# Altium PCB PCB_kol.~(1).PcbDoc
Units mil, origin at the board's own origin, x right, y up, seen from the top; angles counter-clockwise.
Board outline 2952.76 x 2952.76 mil, 4 copper layers (Top Layer, Mid 1 - POWER, Mid 2 - GND, Bottom Layer), stack 61.89 mil thick; 5 components, 17 nets, 134 pads, 1 vias.
Unrouted connection lines stored in the file: 3.
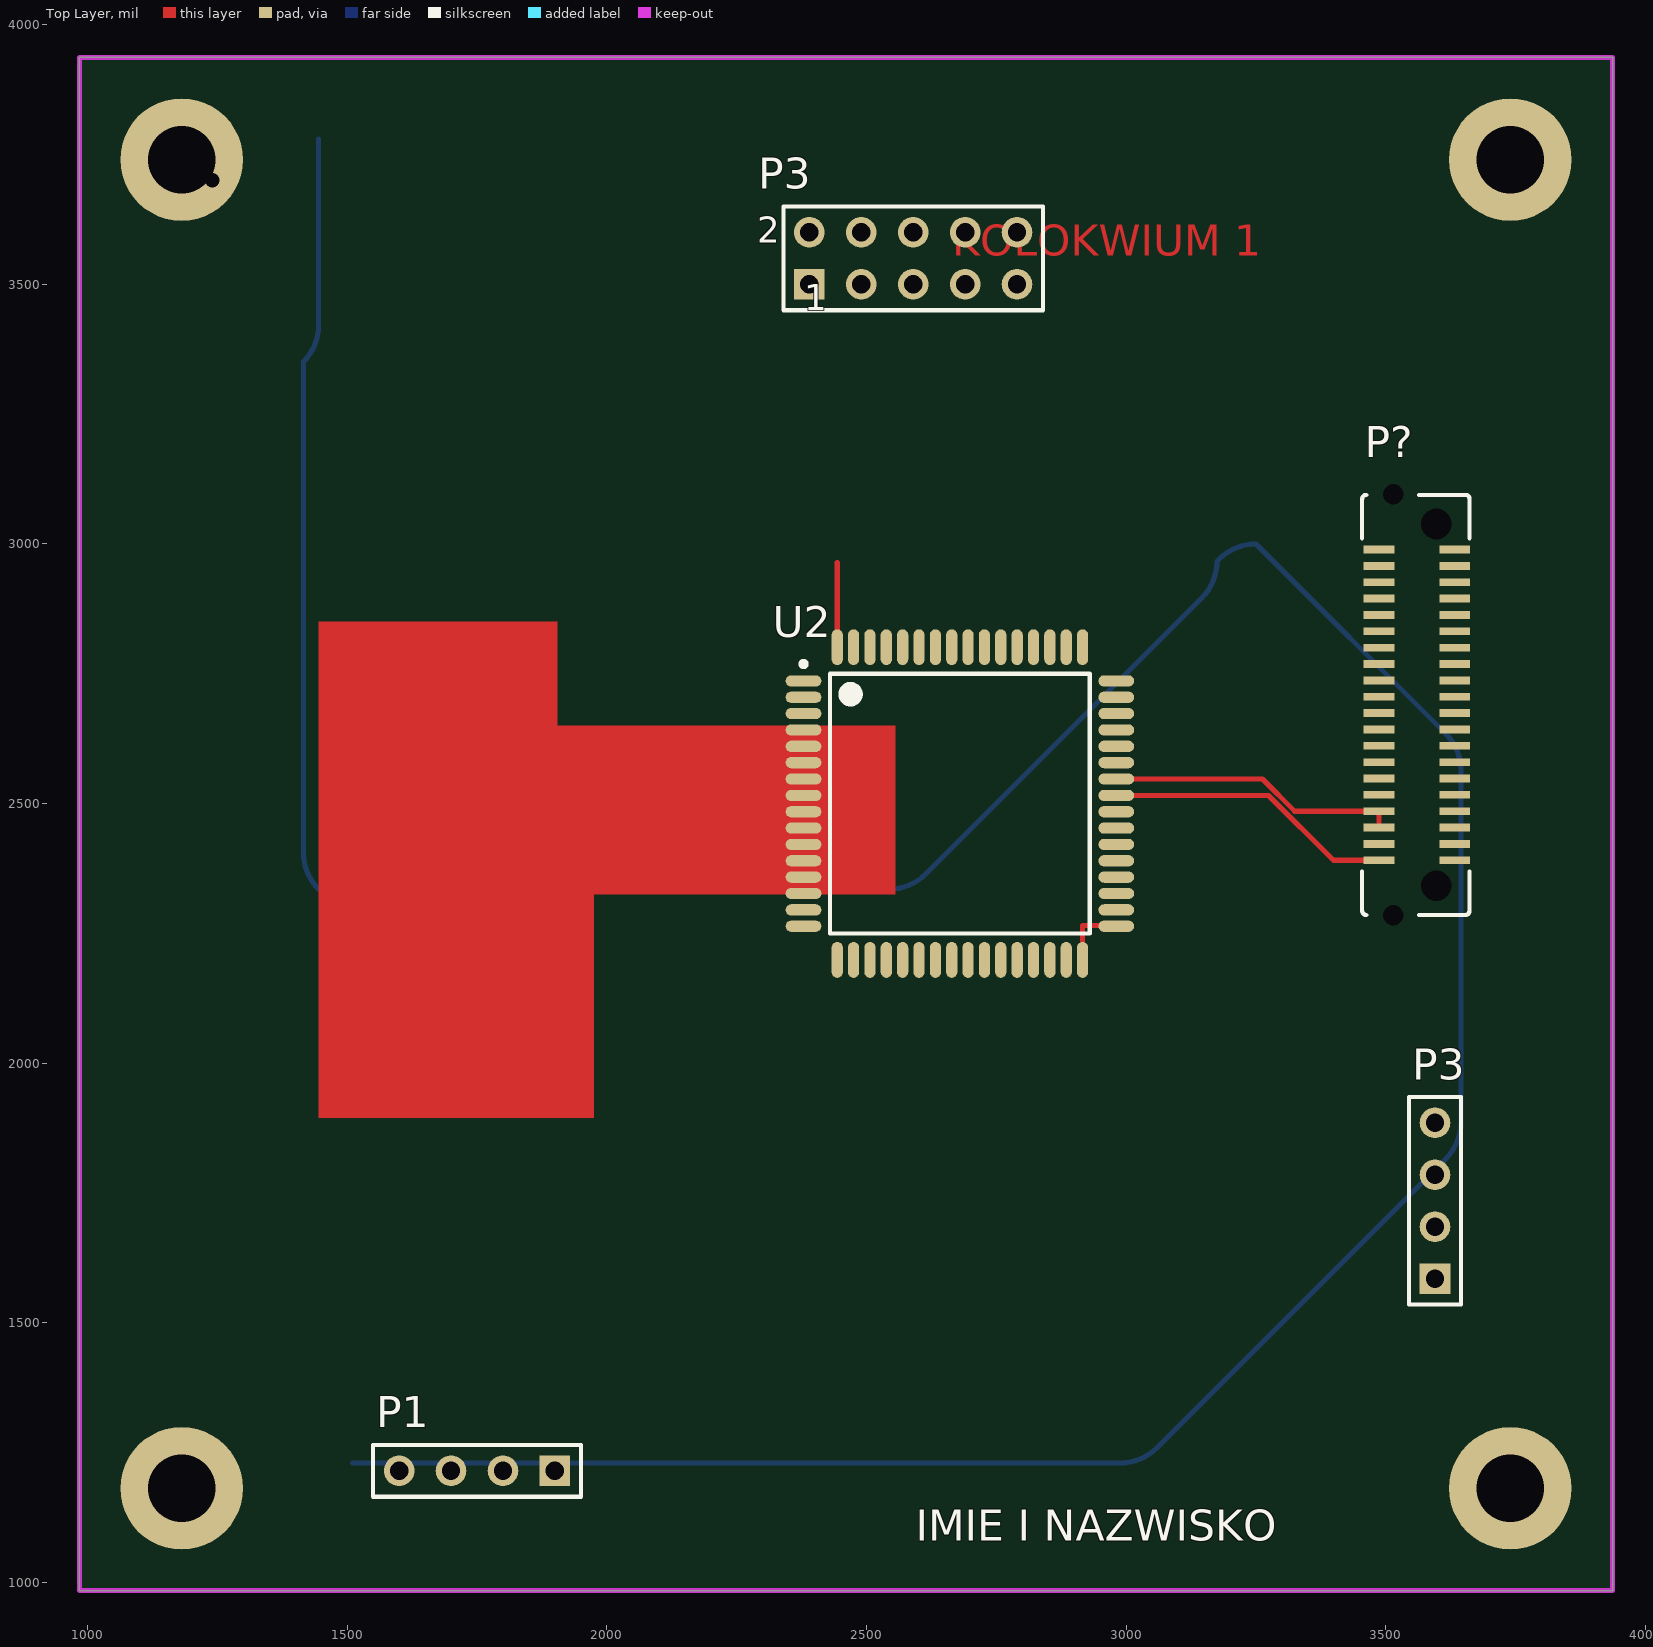
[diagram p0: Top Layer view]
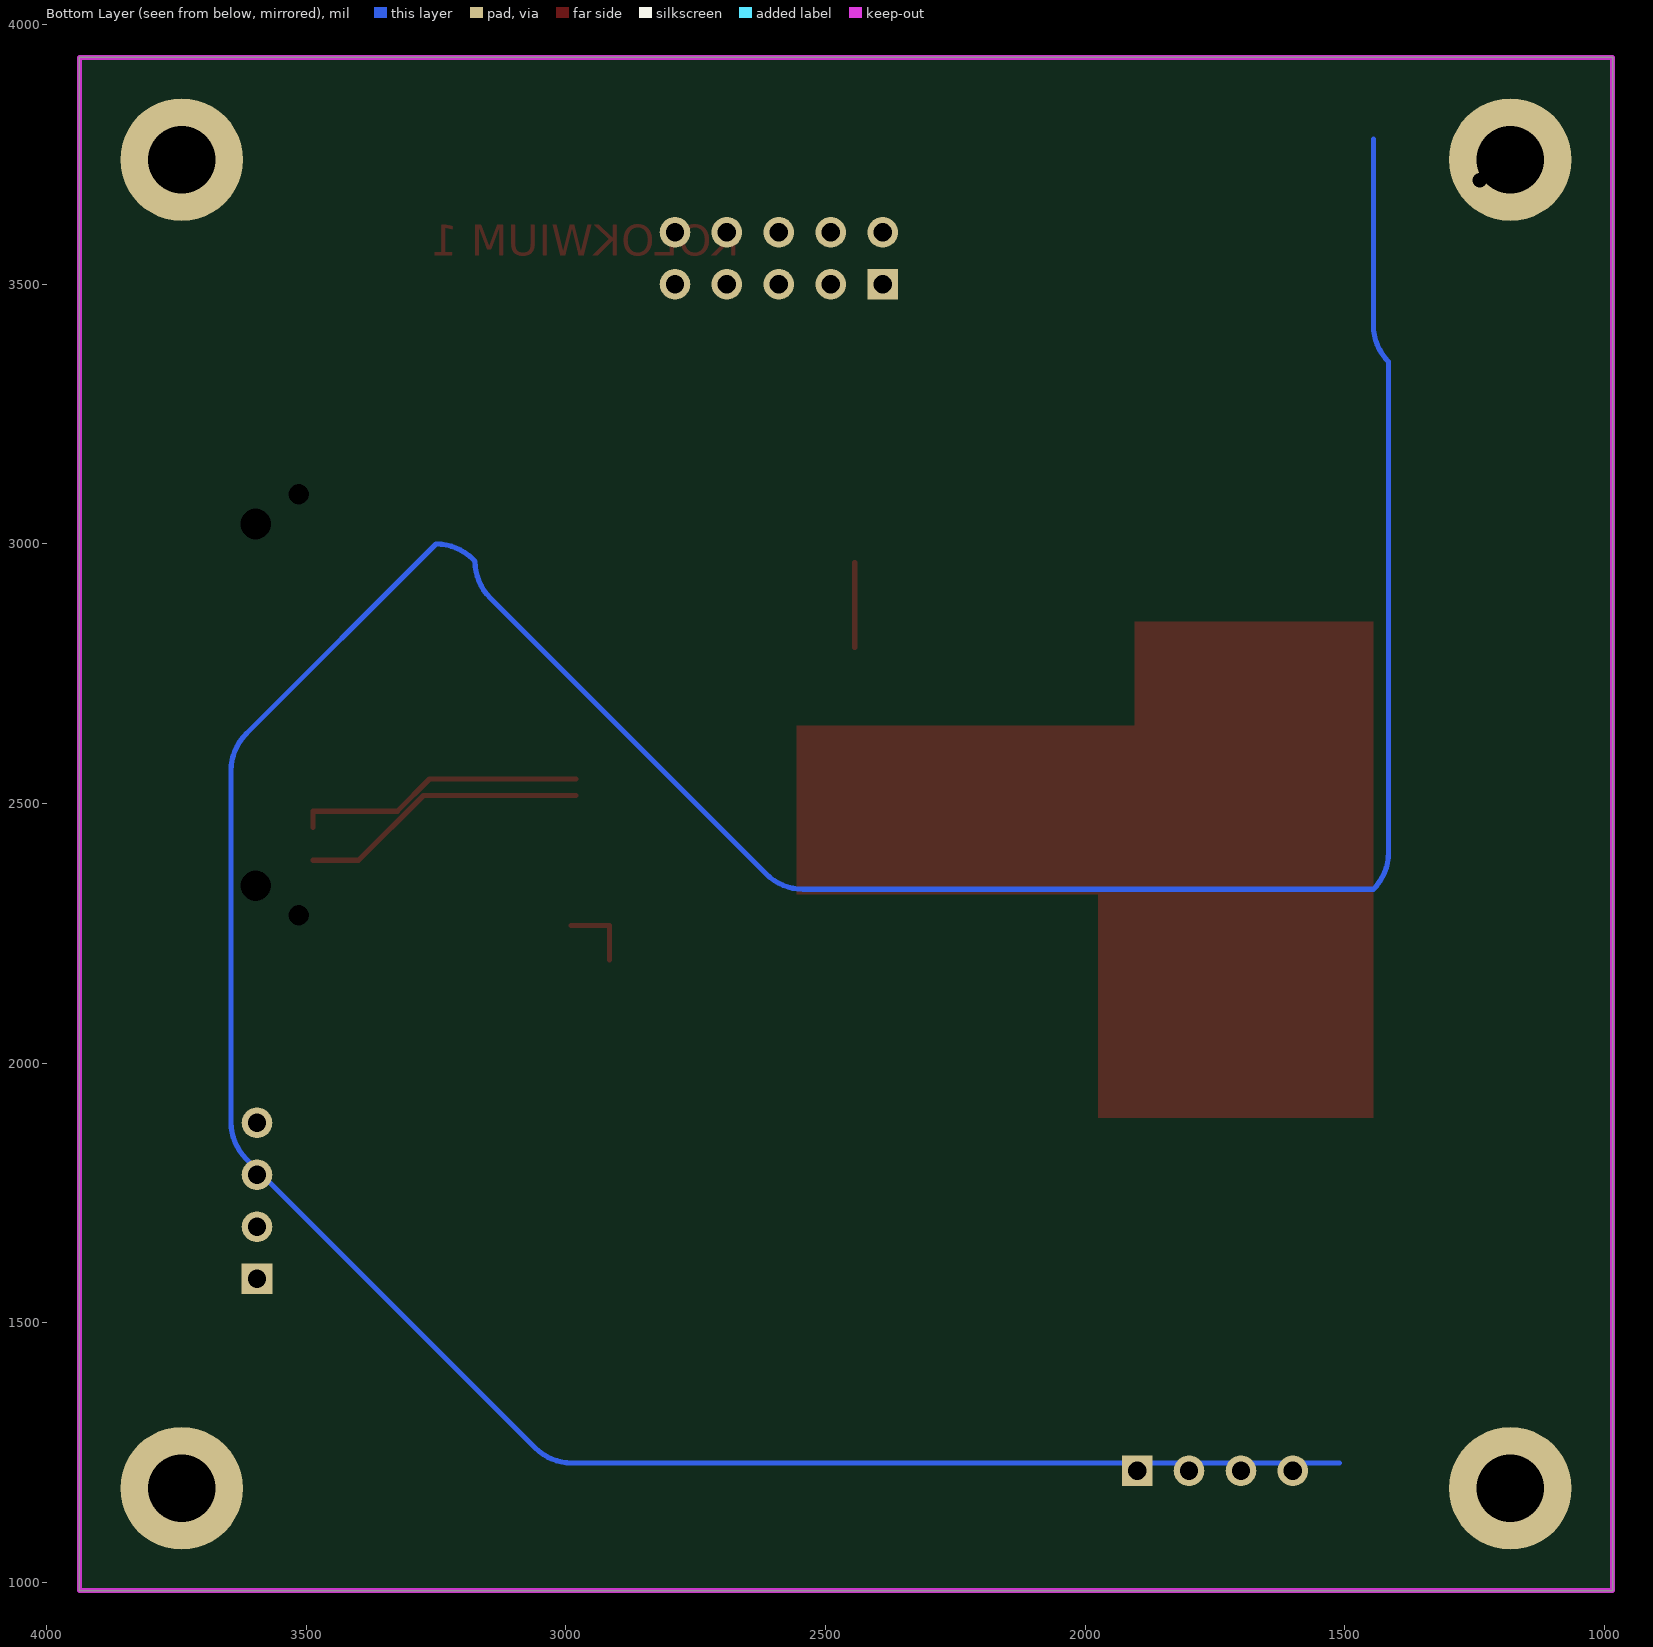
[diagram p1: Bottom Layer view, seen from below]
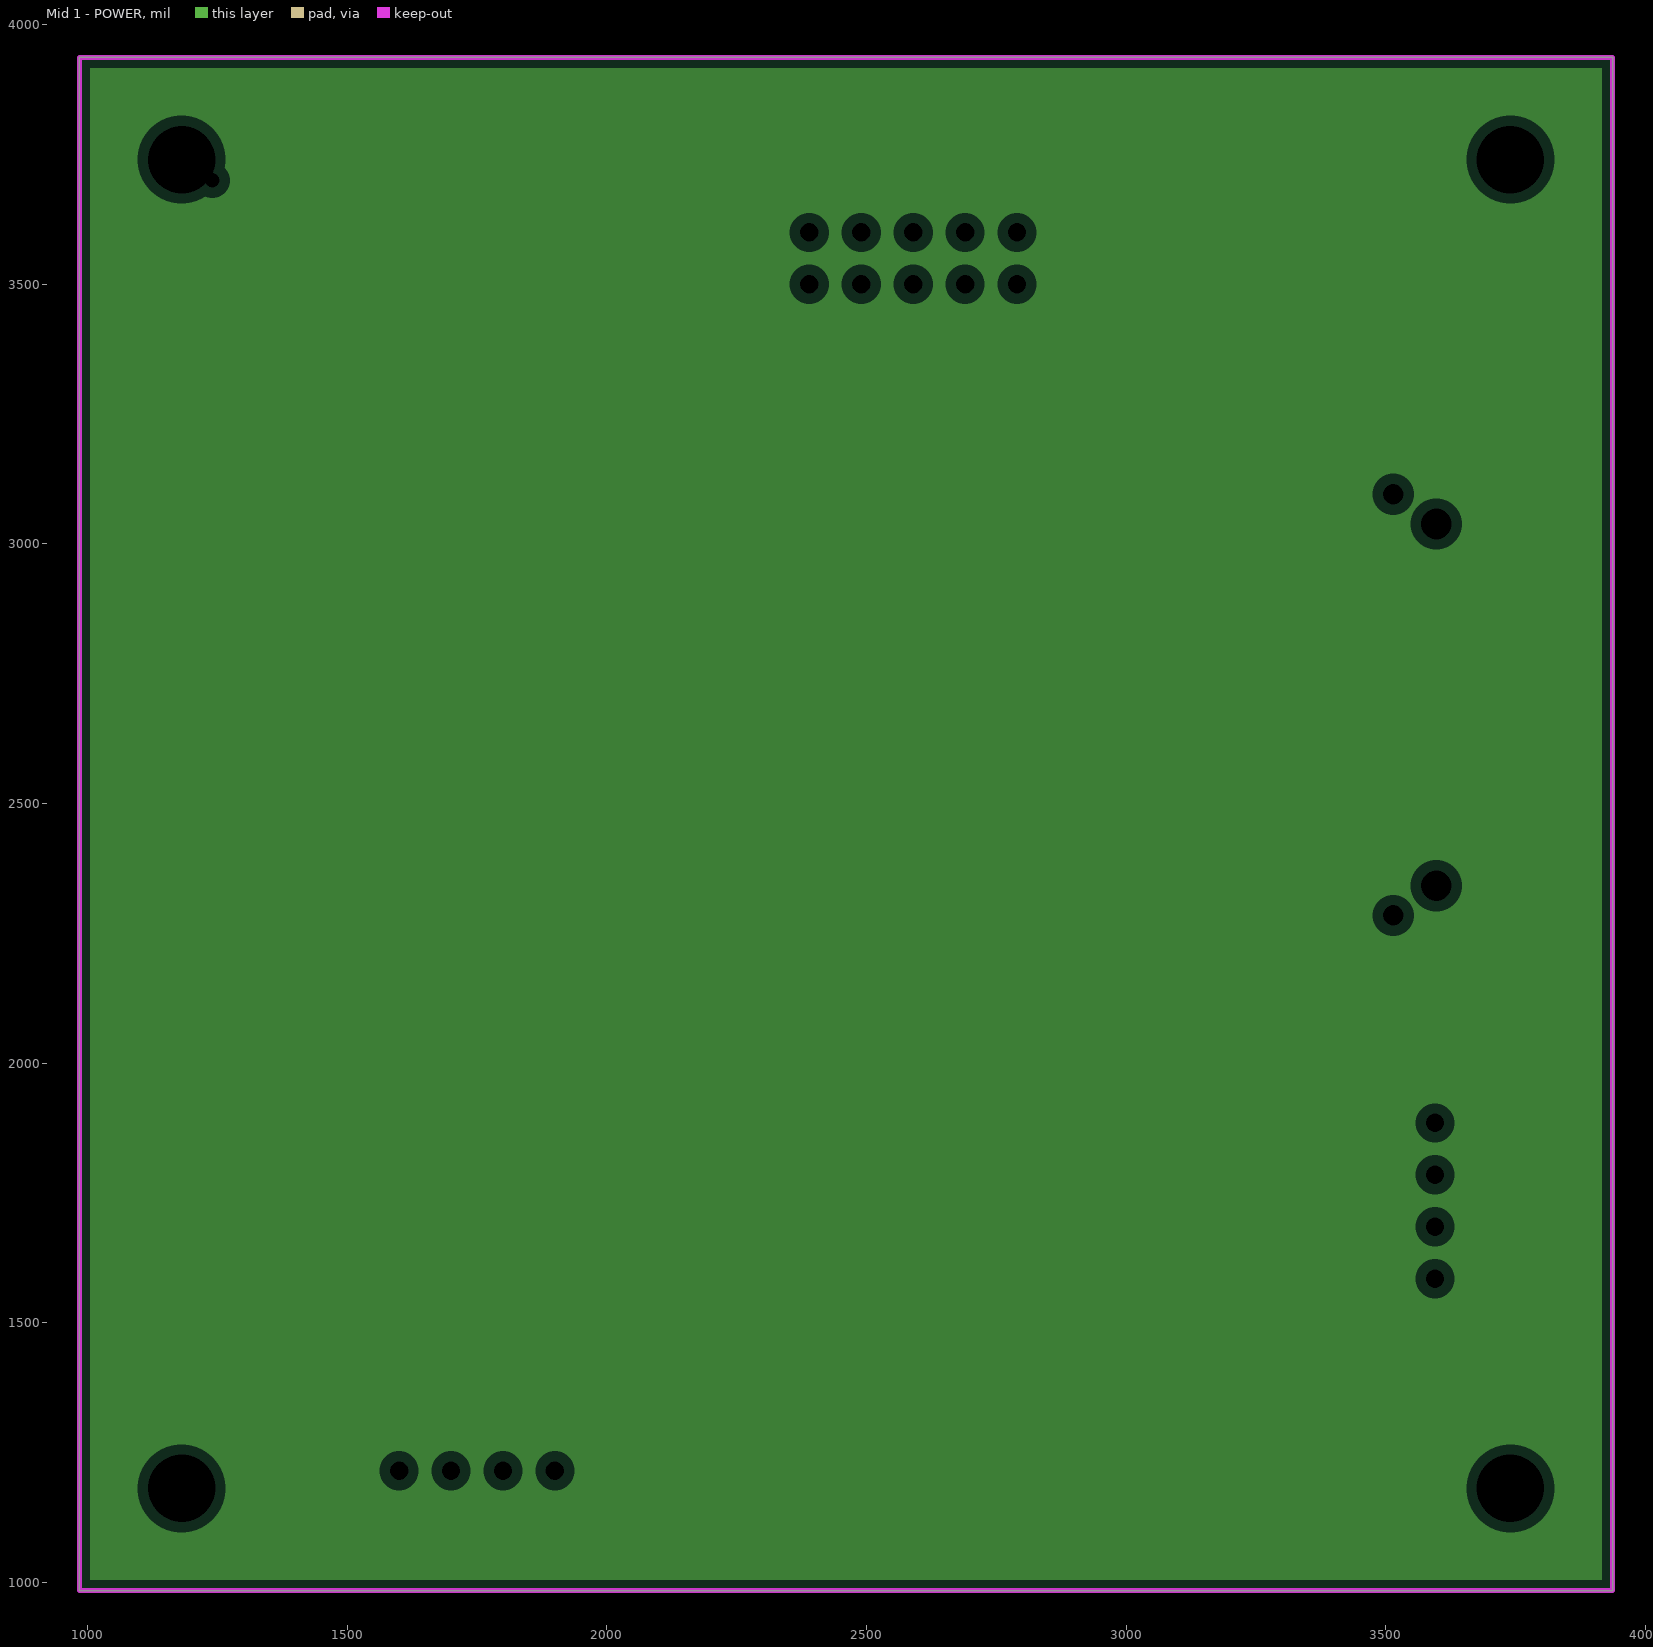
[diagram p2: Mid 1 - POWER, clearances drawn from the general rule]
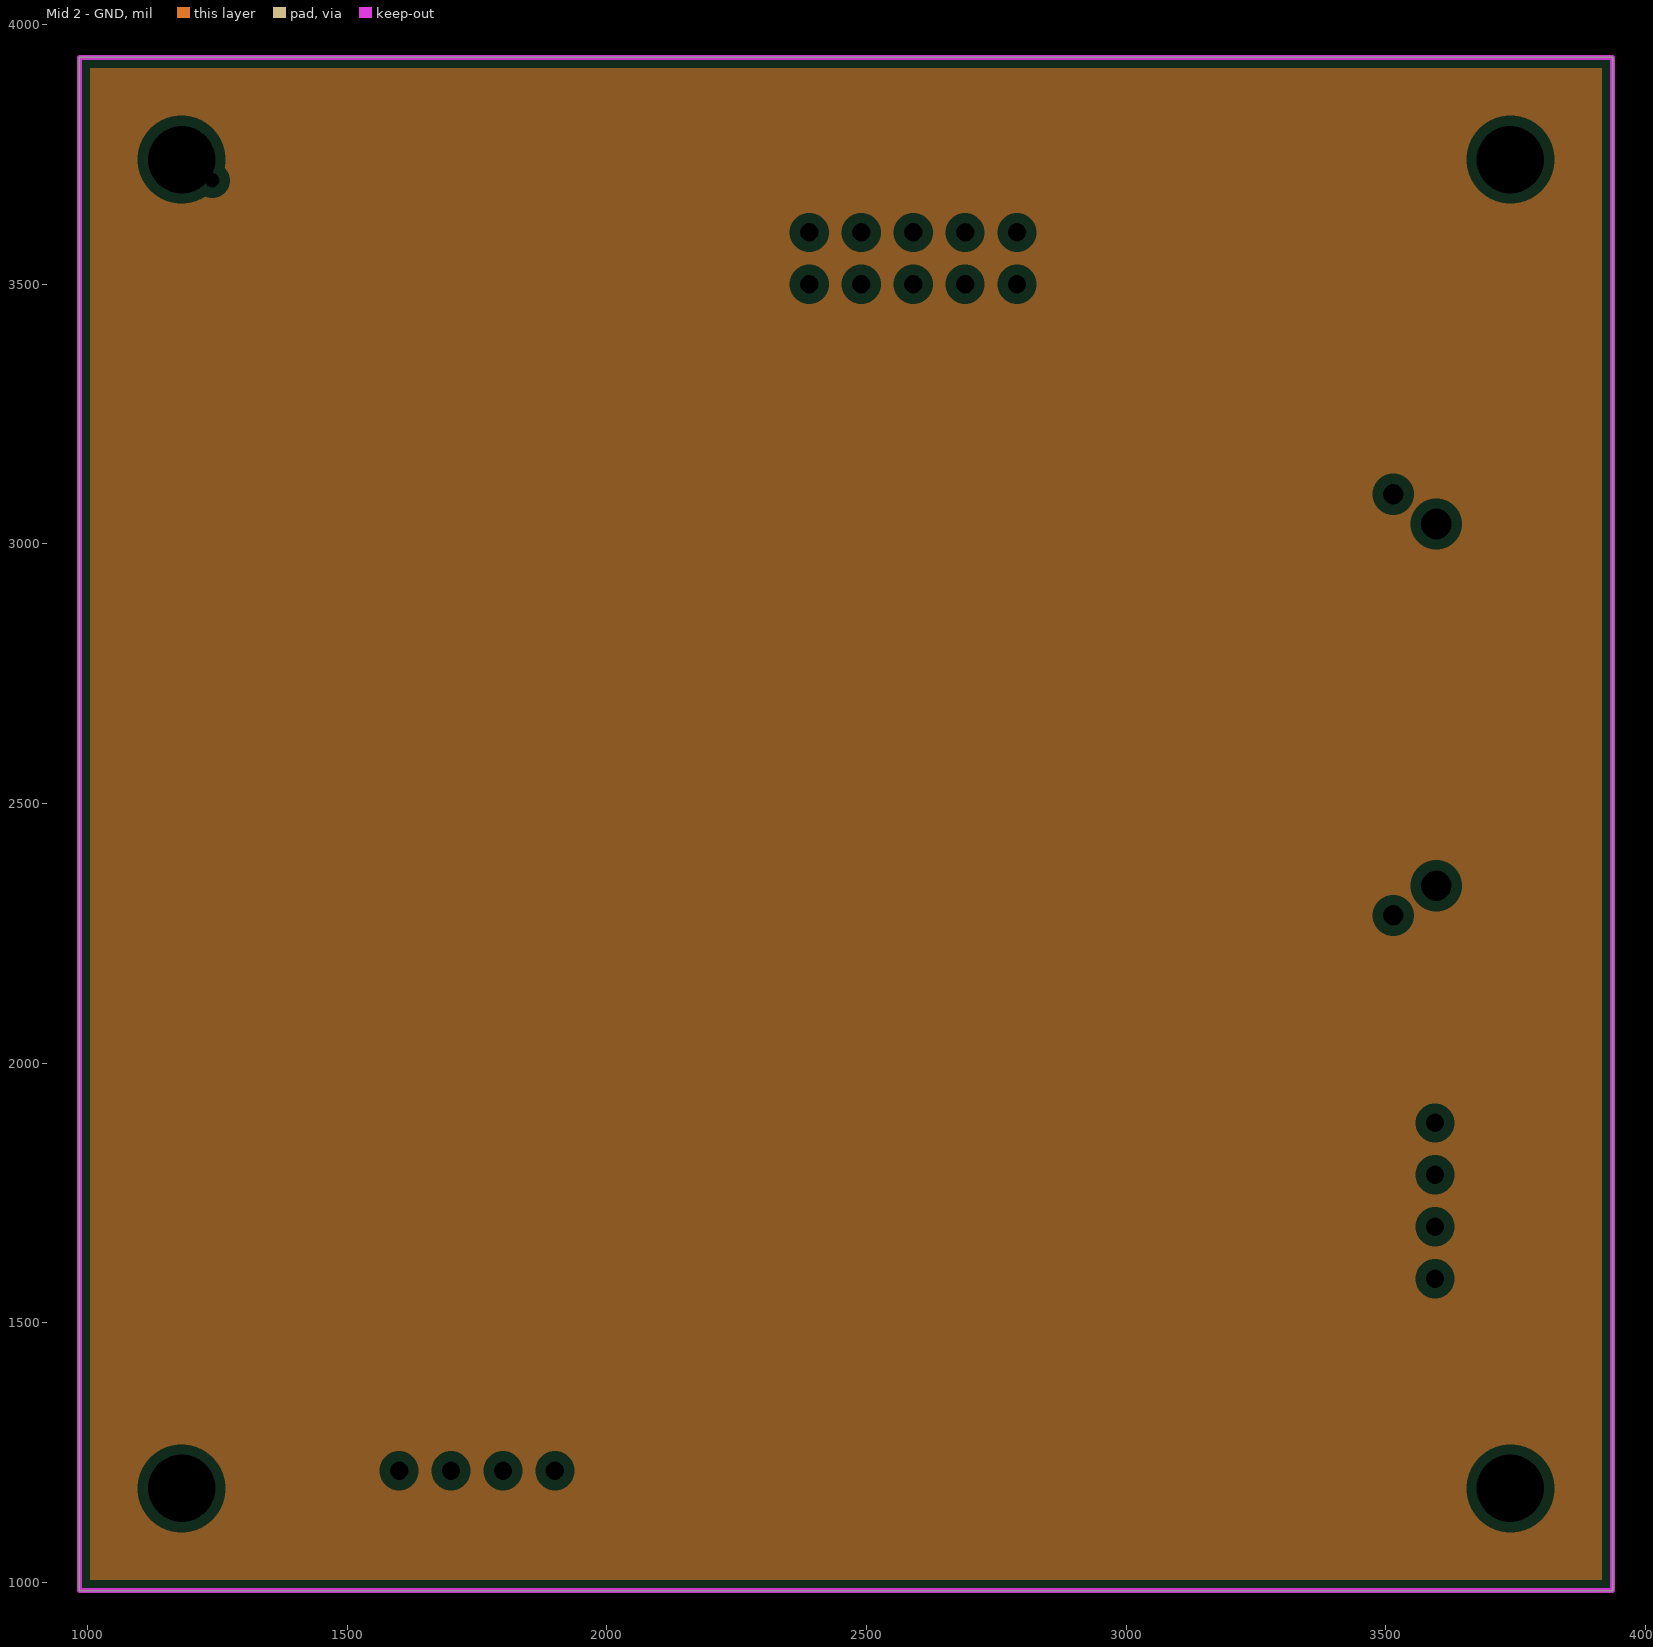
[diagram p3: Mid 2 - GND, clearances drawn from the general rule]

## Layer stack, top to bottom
Top Solder: solder mask 0.4, Solder Resist, Dk 3.5
Top Layer: signal copper 0.7087
Dielectric 1: prepreg 15, Isola DE 104ML, Dk 3.97
Mid 1 - POWER: plane copper 1.378, net GND
Dielectric 2: core 27.7165, Isola DE 104ML, Dk 3.97
Mid 2 - GND: plane copper 1.378, net GND
Dielectric 3: prepreg 15, Isola DE 104ML, Dk 3.97
Bottom Layer: signal copper 0.7087
Bottom Solder: solder mask 0.4, Solder Resist, Dk 3.5

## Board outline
984.25,984.25 3937.01,984.25 3937.01,3937.01 984.25,3937.01

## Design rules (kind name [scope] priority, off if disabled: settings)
Clearance [All] p1: gap=10
PlaneClearance [All] p1: clearance=20
PlaneConnect [All] p1: planeconnectstyle=Relief reliefexpansion=20 reliefentries=4 reliefconductorwidth=10 reliefairgap=10
PolygonConnect [All] p1: connectstyle=Relief reliefconductorwidth=10 reliefentries=4 polygonreliefangle="90 Angle" airgapwidth=10
RoomDefinition Schemat_top [InComponentClass('Schemat_top')] p1: confinementstyle=ConfineIn formatcopy=TRUE lockcomponents=FALSE outline 3280,1050 1240,1050 1240,3670 2040,3670 2040,2050 3280,2050
RoomDefinition U_Processor [InComponentClass('U_Processor')] p2: confinementstyle=ConfineIn formatcopy=TRUE lockcomponents=FALSE outline 3740,2080 2130,2080 2130,3370 3740,3370
RoutingVias [All] p1: holewidth=28 width=50 viastyle="Through Hole" minholewidth=28 minwidth=50 maxholewidth=28 maxwidth=50
SolderMaskExpansion [All] p1: expansion=4
Width [All] p1: maxlimit=10 minlimit=10 preferedwidth=10
28 further rules are at their usual default settings.

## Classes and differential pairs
component class Schemat_top: P1 P3 P?
component class U_Processor: C? U2

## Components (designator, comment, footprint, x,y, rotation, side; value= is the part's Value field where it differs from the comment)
P1 "Header 4" HDR1X4 1900,1215 r180 top
P3 "Header 5X2" HDR2X5 2390,3500 r0 top
P3 "Header 4" HDR1X4 3595,1585 r90 top
P? "SAMTEC LSEM 40-pin" LSEM-120-03.0-L-DV-A-N-K-TR 3560,2690 r90 top
U2 "ATmega128-16AU" 64A_N 2680,2500 r0 top

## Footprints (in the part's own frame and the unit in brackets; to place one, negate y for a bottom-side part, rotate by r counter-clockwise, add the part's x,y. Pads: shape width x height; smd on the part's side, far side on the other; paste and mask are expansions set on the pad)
64A_N [mm] "Thin QFP, 64-Leads, Body 14x14mm, Pitch 0.8mm, IPC Medium Density"
  oval 1.75x0.55 smd: 1(-7.65,6) 2(-7.65,5.2) 3(-7.65,4.4) 4(-7.65,3.6) 5(-7.65,2.8) 6(-7.65,2) 7(-7.65,1.2) 8(-7.65,0.4) 9(-7.65,-0.4) 10(-7.65,-1.2) 11(-7.65,-2) 12(-7.65,-2.8) 13(-7.65,-3.6) 14(-7.65,-4.4) 15(-7.65,-5.2) 16(-7.65,-6) 33(7.65,-6) 34(7.65,-5.2) 35(7.65,-4.4) 36(7.65,-3.6) 37(7.65,-2.8) 38(7.65,-2) 39(7.65,-1.2) 40(7.65,-0.4) 41(7.65,0.4) 42(7.65,1.2) 43(7.65,2) 44(7.65,2.8) 45(7.65,3.6) 46(7.65,4.4) 47(7.65,5.2) 48(7.65,6)
  oval 0.55x1.75 smd: 17(-6,-7.65) 18(-5.2,-7.65) 19(-4.4,-7.65) 20(-3.6,-7.65) 21(-2.8,-7.65) 22(-2,-7.65) 23(-1.2,-7.65) 24(-0.4,-7.65) 25(0.4,-7.65) 26(1.2,-7.65) 27(2,-7.65) 28(2.8,-7.65) 29(3.6,-7.65) 30(4.4,-7.65) 31(5.2,-7.65) 32(6,-7.65) 49(6,7.65) 50(5.2,7.65) 51(4.4,7.65) 52(3.6,7.65) 53(2.8,7.65) 54(2,7.65) 55(1.2,7.65) 56(0.4,7.65) 57(-0.4,7.65) 58(-1.2,7.65) 59(-2,7.65) 60(-2.8,7.65) 61(-3.6,7.65) 62(-4.4,7.65) 63(-5.2,7.65) 64(-6,7.65)
  silkscreen extent -7.77,-6.35 6.35,6.95, body extent -7,-7 7,7, height 1.2
HDR1X4 [mm] "Connector; Header; 4 Position"
  rect 1.5x1.5 hole 0.9: 1(0,0)
  round 1.5 hole 0.9: 2(2.54,0) 3(5.08,0) 4(7.62,0)
  silkscreen extent -1.27,-1.27 8.89,1.27
HDR2X5 [mm] "Connector; Header; 5x2 Position"
  rect 1.5x1.5 hole 0.9: 1(0,0)
  round 1.5 hole 0.9: 2(0,2.54) 3(2.54,0) 4(2.54,2.54) 5(5.08,0) 6(5.08,2.54) 7(7.62,0) 8(7.62,2.54) 9(10.16,0) 10(10.16,2.54)
  silkscreen extent -1.27,-1.27 11.43,3.81
LSEM-120-03.0-L-DV-A-N-K-TR [mm] "LSEM 0.8mm Razor Beam Hermaphroditic Connector 40-pin"
  round 0 hole 1 unplated: 0(-10.3,1.15) 0(10.3,1.15)
  round 2 on Top Paste paste+2: 0(-10.3,1.15) 0(10.3,1.15)
  round 2.1 on Top Solder paste+2: 0(-10.3,1.15) 0(10.3,1.15)
  round 0 hole 1.5 unplated: 0(-8.85,-0.95) 0(8.85,-0.95)
  rect 0.38x1.5 smd: 1(7.6,-1.85) 2(7.6,1.85) 3(6.8,-1.85) 4(6.8,1.85) 5(6,-1.85) 6(6,1.85) 7(5.2,-1.85) 8(5.2,1.85) 9(4.4,-1.85) 10(4.4,1.85) 11(3.6,-1.85) 12(3.6,1.85) 13(2.8,-1.85) 14(2.8,1.85) 15(2,-1.85) 16(2,1.85) 17(1.2,-1.85) 18(1.2,1.85) 19(0.4,-1.85) 20(0.4,1.85) 21(-0.4,-1.85) 22(-0.4,1.85) 23(-1.2,-1.85) 24(-1.2,1.85) 25(-2,-1.85) 26(-2,1.85) 27(-2.8,-1.85) 28(-2.8,1.85) 29(-3.6,-1.85) 30(-3.6,1.85) 31(-4.4,-1.85) 32(-4.4,1.85) 33(-5.2,-1.85) 34(-5.2,1.85) 35(-6,-1.85) 36(-6,1.85) 37(-6.8,-1.85) 38(-6.8,1.85) 39(-7.6,-1.85) 40(-7.6,1.85)
  silkscreen extent -10.28,-2.57 10.28,2.68, body extent -10.2,-2.7 10.2,2.8, height 4.58

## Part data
P1 P3: "Header, 4-Pin"
P3: "Header, 5-Pin, Dual row"
P?: "Component desciption"
U2: "8-bit AVR Microcontroller, 4.5-5.5V, 128KB Flash, 4KB EEPROM, 4KB SRAM, 64-pin TQFP, Industrial Grade (-40°C to 85°C)"

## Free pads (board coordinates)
  round 236.22 hole 129.92: 0(1181.1,1181.1) 0(1181.1,3740.16) 0(3740.16,1181.1) 0(3740.16,3740.16)

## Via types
v1: diameter 50, hole 28, Top Layer to Bottom Layer, 1 vias

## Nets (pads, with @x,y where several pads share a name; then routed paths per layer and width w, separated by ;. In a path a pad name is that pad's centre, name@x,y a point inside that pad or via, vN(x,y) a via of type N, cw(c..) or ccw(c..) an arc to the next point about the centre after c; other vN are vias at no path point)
5V0: 
BUS1: U2.51
BUS2: U2.50
BUS3: U2.49
BUS4: U2.47 U2.48
BUS5: U2.46
BUS6: U2.45
BUS7: U2.44
CONTROL1: P?.40 U2.41 | length 557.7
  Top Layer w10: U2.41 3274.25,2515.75 3399.21,2390.79 P?.40
CONTROL2: P?.36 U2.42 | length 563.1
  Top Layer w10: U2.42 3262.76,2547.24 3324.72,2485.28 3487.17,2485.28 P?.36
GND: U2.63
RESET: U2.20
TCK: U2.57
TDI: U2.54
TDO: U2.55
TMS: U2.56
VCC: U2.21 U2.62 U2.64 | length 162.6
  Top Layer w10: U2.64 2443.78,2963.78
pads on no net: P1.1 P1.2 P1.3 P1.4 P3.1 P3.2 P3.3 P3.4 P3.5 P3.6 P3.7 P3.8 P3.9 P3.10 P?.0 P?.1 P?.2 P?.3 P?.4 P?.5 P?.6 P?.7 P?.8 P?.9 P?.10 P?.11 P?.12 P?.13 P?.14 P?.15 P?.16 P?.17 P?.18 P?.19 P?.20 P?.21 P?.22 P?.23 P?.24 P?.25 P?.26 P?.27 P?.28 P?.29 P?.30 P?.31 P?.32 P?.33 P?.34 P?.35 P?.37 P?.38 P?.39 U2.1 U2.2 U2.3 U2.4 U2.5 U2.6 U2.7 U2.8 U2.9 U2.10 U2.11 U2.12 U2.13 U2.14 U2.15 U2.16 U2.17 U2.18 U2.19 U2.22 U2.23 U2.24 U2.25 U2.26 U2.27 U2.28 U2.29 U2.30 U2.31 U2.32 U2.33 U2.34 U2.35 U2.36 U2.37 U2.38 U2.39 U2.40 U2.43 U2.52 U2.53 U2.58 U2.59 U2.60 U2.61
copper on no net: | length 7387.9
  Top Layer w10: 2916.22,2198.82 2916.22,2265 2990,2265
  Bottom Layer w10: 1445,3780 1445,3421.42 cw(c1345,3421.42) 1415.71,3350.71 1415.71,2405.71 ccw(c1515.71,2405.71) 1445,2335 2543.58,2335 ccw(c2543.58,2435) 2614.29,2364.29 3145.71,2895.71 ccw(c3075,2966.42) 3175,2966.42 3179.29,2970.71 cw(c3250,2900) 3250,3000 3615.71,2634.29 cw(c3545,2563.58) 3645,2563.58 3645,1886.42 cw(c3545,1886.42) 3615.71,1815.71 3059.29,1259.29 cw(c2988.58,1330) 2988.58,1230 1510,1230
  other v1: 1240,3700

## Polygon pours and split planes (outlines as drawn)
GND on Mid 1 - POWER (split plane): 3916.91,1004.35 1004.35,1004.35 1004.35,3916.91 3916.91,3916.91
GND on Mid 2 - GND (split plane): 3916.91,1004.35 1004.35,1004.35 1004.35,3916.91 3916.91,3916.91

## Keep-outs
Keep-Out Layer:
  the board outline again, w10

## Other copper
Top Layer:
  region: 1445,2850 1445,1895 1975,1895 1975,2325 2555,2325 2555,2650 1905,2650 1905,2850
  text "KOLOKWIUM 1" at 2665,3555 h60

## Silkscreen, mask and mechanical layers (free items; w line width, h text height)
Top Overlay:
  text "IMIE I NAZWISKO" at 2595,1080 h60

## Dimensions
1181.1,3740.16 to 3740.16,3740.16 on M5 Dimensions
3937.01,984.25 to 3937.01,3937.01 on M5 Dimensions
984.25,984.25 to 3937.01,984.25 on M5 Dimensions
